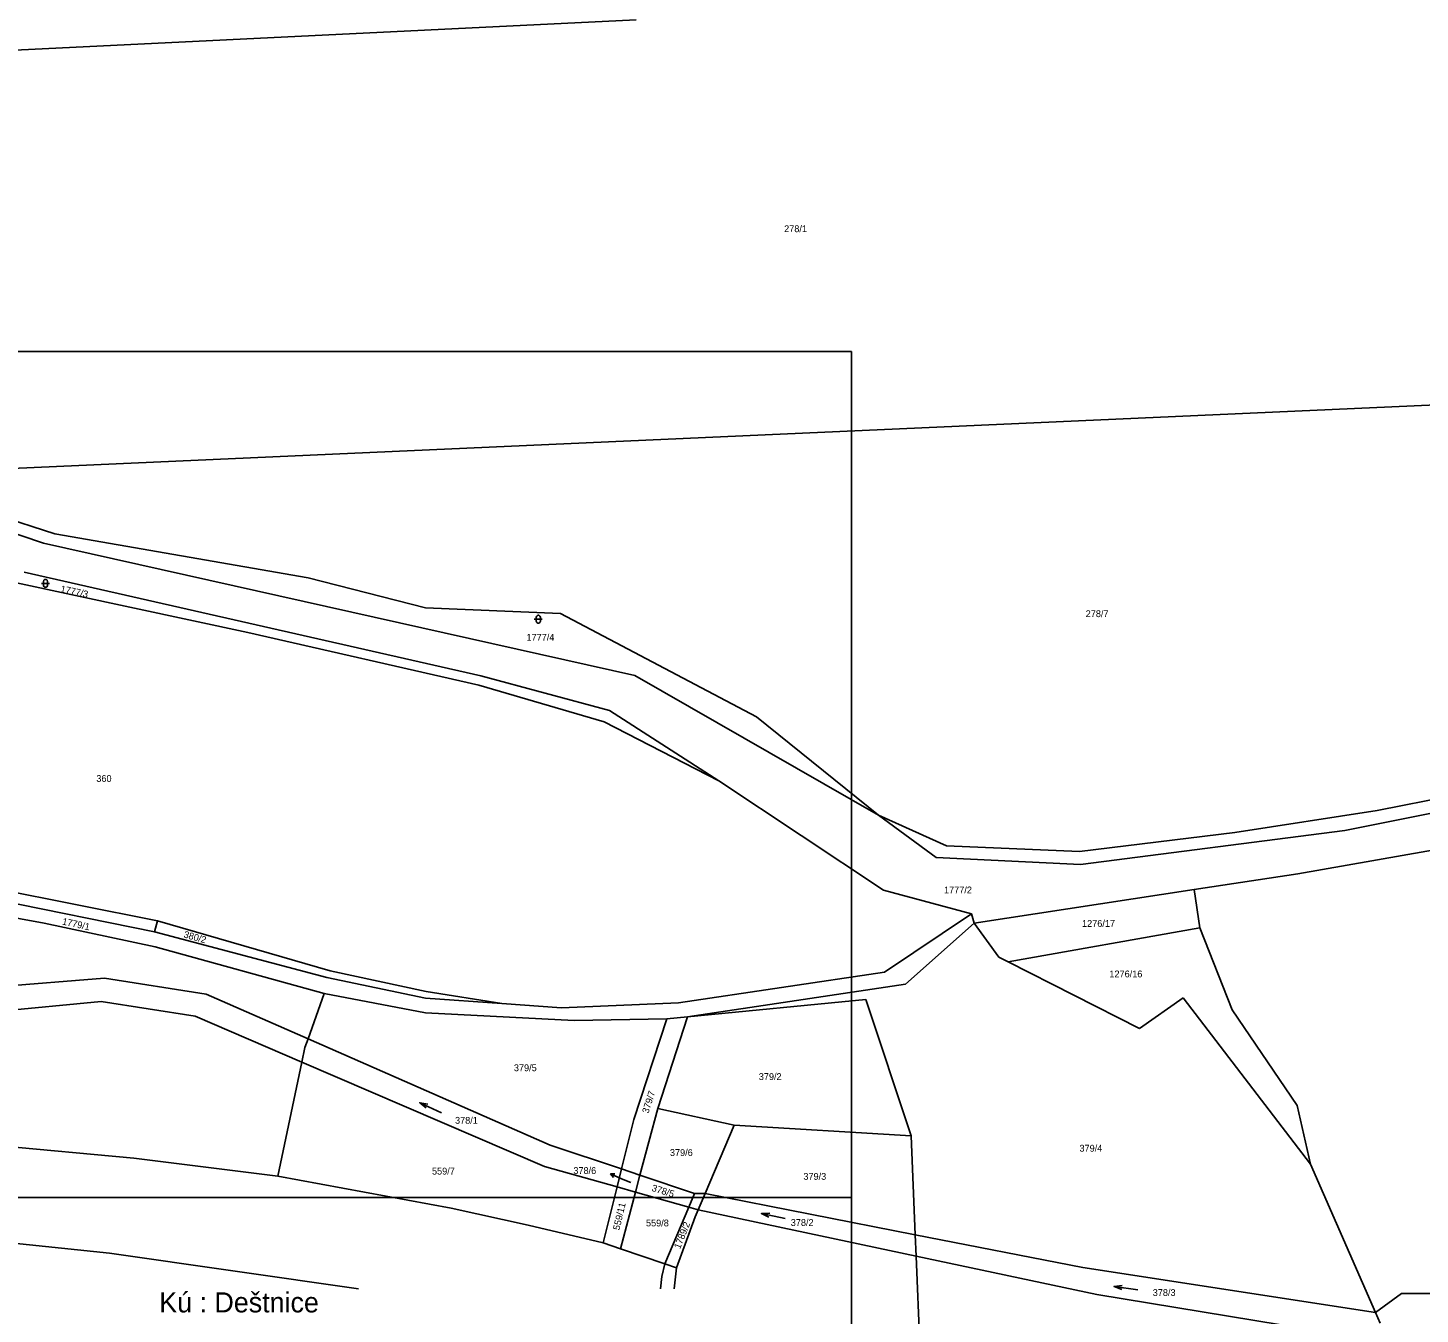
# Model space of a CAD drawing. Extents: x -799786 to -795190, y -1021716 to -1017834.
# Drawn here: x -798625.3 to -798278.5, y -1019029 to -1018708.6 of the extents above; entities that cross this region are included whole.
import ezdxf

# ---------------------------------------------------------------- set-up
doc = ezdxf.new("R2010")
doc.units = 0
for name, color, linetype in [('Default', 7, 'Continuous'), ('KLADY_ZMVM', 7, 'Continuous'), ('KN_HRANICE', 7, 'Continuous'), ('KN_KULTURY', 7, 'Continuous'), ('KN_PARCELY', 7, 'Continuous'), ('KN_SLUCKY', 7, 'Continuous'), ('LEGENDA', 7, 'Continuous')]:
    doc.layers.add(name, color=color, linetype=linetype)

# ---------------------------------------------------------------- blocks, each defined once
blk = doc.blocks.new('316')
at = {"layer": 'Default'}
for points in [[(-1, 1), (0.27, 1), (1, 1)], [(-0.5, 1.5), (-0.4, 1.79), (-0.15, 1.97), (0.16, 1.97), (0.41, 1.79), (0.51, 1.5), (0.51, 0.5), (0.41, 0.21), (0.16, 0.03), (-0.15, 0.03), (-0.4, 0.21), (-0.5, 0.5), (-0.5, 1.5)]]:
    blk.add_lwpolyline(points, dxfattribs=at)
blk = doc.blocks.new('802')
at = {"layer": 'Default'}
blk.add_line((-3, 0), (3, 0), dxfattribs=at)
blk.add_lwpolyline([(1, 0.5), (3, 0), (1, -0.5)], dxfattribs=at)
blk = doc.blocks.new('10292')
at = {"layer": 'Default'}
blk.add_line((0, 3), (0, 0), dxfattribs=at)
blk.add_lwpolyline([(-0.5, 2), (0, 3), (0.5, 2)], dxfattribs=at)

msp = doc.modelspace()

# ---------------------------------------------------------------- linework, layer by layer
at = {"layer": 'KLADY_ZMVM'}
msp.add_lwpolyline([(-799375, -1019000), (-798750, -1019000), (-798420.18, -1019000)], dxfattribs=at)
at = {"layer": 'KN_HRANICE'}
for p, q in [((-798628.58, -1018714.18), (-798473.83, -1018706.61)), ((-798648.58, -1018819.28), (-798164.43, -1018797.57)), ((-798670.97, -1018817.82), (-798618.58, -1018834.64)), ((-798670.05, -1018820.82), (-798621.41, -1018836.96)), ((-798621.41, -1018836.96), (-798474.17, -1018869.95)), ((-798618.58, -1018834.64), (-798555.54, -1018845.61)), ((-798628.2, -1018846.85), (-798570.58, -1018859.25)), ((-798626.28, -1018844.22), (-798512.51, -1018870.06)), ((-798555.54, -1018845.61), (-798526.25, -1018853.09)), ((-798526.25, -1018853.09), (-798492.65, -1018854.49)), ((-798492.65, -1018854.49), (-798443.82, -1018880.26)), ((-798570.58, -1018859.25), (-798513.02, -1018872.39)), ((-798512.51, -1018870.06), (-798480.48, -1018878.64)), ((-798474.17, -1018869.95), (-798413.42, -1018904.71)), ((-798513.02, -1018872.39), (-798481.79, -1018881.47)), ((-798289.26, -1018903.57), (-798140.92, -1018874.27)), ((-798480.48, -1018878.64), (-798453.21, -1018896.22)), ((-798481.79, -1018881.47), (-798453.21, -1018896.22)), ((-798443.82, -1018880.26), (-798413.42, -1018904.71)), ((-798297.3, -1018908.51), (-798181.63, -1018885.44)), ((-798453.21, -1018896.22), (-798412.19, -1018923.42)), ((-798413.42, -1018904.71), (-798399.11, -1018915.28)), ((-798413.42, -1018904.71), (-798396.51, -1018912.35)), ((-798324.7, -1018909.02), (-798289.26, -1018903.57)), ((-798309.02, -1018919.33), (-798225.73, -1018904.69)), ((-798363.41, -1018913.79), (-798324.7, -1018909.02)), ((-798363.16, -1018917), (-798297.3, -1018908.51)), ((-798396.51, -1018912.35), (-798363.41, -1018913.79)), ((-798399.11, -1018915.28), (-798363.16, -1018917)), ((-798334.83, -1018923.26), (-798309.02, -1018919.33)), ((-798646.5, -1018923.14), (-798593.8, -1018933.78)), ((-798644.85, -1018920.76), (-798593.08, -1018931.09)), ((-798412.19, -1018923.42), (-798390.27, -1018929.32)), ((-798389.65, -1018931.6), (-798334.83, -1018923.26)), ((-798333.38, -1018932.83), (-798334.83, -1018923.26)), ((-798646.74, -1018926.95), (-798621.31, -1018931.61)), ((-798411.98, -1018943.8), (-798390.27, -1018929.32)), ((-798390.27, -1018929.32), (-798389.65, -1018931.6)), ((-798621.31, -1018931.61), (-798593.59, -1018937.5)), ((-798593.08, -1018931.09), (-798593.8, -1018933.78)), ((-798593.8, -1018933.78), (-798550.83, -1018945.14)), ((-798593.08, -1018931.09), (-798550.03, -1018943.53)), ((-798406.71, -1018946.8), (-798389.65, -1018931.6)), ((-798383.44, -1018940.08), (-798389.65, -1018931.6)), ((-798333.38, -1018932.83), (-798381.11, -1018941.26)), ((-798593.59, -1018937.5), (-798551.56, -1018949.18)), ((-798381.11, -1018941.26), (-798383.44, -1018940.08)), ((-798550.03, -1018943.53), (-798526.1, -1018948.66)), ((-798463.3, -1018951.51), (-798411.98, -1018943.8)), ((-798348.39, -1018957.83), (-798381.11, -1018941.26)), ((-798653.61, -1018949.12), (-798606.28, -1018945.31)), ((-798606.28, -1018945.31), (-798580.93, -1018949.34)), ((-798550.83, -1018945.14), (-798526.25, -1018950.31)), ((-798461.06, -1018954.98), (-798406.71, -1018946.8)), ((-798639.41, -1018954.22), (-798607.1, -1018951.14)), ((-798607.1, -1018951.14), (-798583.64, -1018954.81)), ((-798580.93, -1018949.34), (-798555.55, -1018960.46)), ((-798551.56, -1018949.18), (-798555.55, -1018960.46)), ((-798551.56, -1018949.18), (-798526.25, -1018953.93)), ((-798526.25, -1018950.31), (-798507.23, -1018951.65)), ((-798526.1, -1018948.66), (-798507.23, -1018951.65)), ((-798492.44, -1018952.69), (-798463.3, -1018951.51)), ((-798461.06, -1018954.98), (-798416.56, -1018950.62)), ((-798405.32, -1018984.59), (-798416.56, -1018950.62)), ((-798337.55, -1018950.26), (-798348.39, -1018957.83)), ((-798305.84, -1018991.62), (-798337.55, -1018950.26)), ((-798583.64, -1018954.81), (-798557.08, -1018966.24)), ((-798526.25, -1018953.93), (-798489.23, -1018955.9)), ((-798507.23, -1018951.65), (-798492.44, -1018952.69)), ((-798468.45, -1018977.76), (-798461.06, -1018954.98)), ((-798466.19, -1018955.48), (-798461.06, -1018954.98)), ((-798489.23, -1018955.9), (-798466.19, -1018955.48)), ((-798466.19, -1018955.48), (-798474.39, -1018980.52)), ((-798555.55, -1018960.46), (-798556.31, -1018962.63)), ((-798555.55, -1018960.46), (-798495.22, -1018986.9)), ((-798556.31, -1018962.63), (-798557.08, -1018966.24)), ((-798557.08, -1018966.24), (-798563.11, -1018994.64)), ((-798557.08, -1018966.24), (-798496.64, -1018992.23)), ((-798468.45, -1018977.76), (-798472.87, -1018994.39)), ((-798449.39, -1018981.94), (-798468.45, -1018977.76)), ((-798474.39, -1018980.52), (-798477.47, -1018992.85)), ((-798449.39, -1018981.94), (-798456.64, -1018999)), ((-798449.39, -1018981.94), (-798405.32, -1018984.59)), ((-798659.98, -1018984.53), (-798598.93, -1018990.13)), ((-798404.31, -1019009.25), (-798405.32, -1018984.59)), ((-798495.22, -1018986.9), (-798477.47, -1018992.85)), ((-798598.93, -1018990.13), (-798563.11, -1018994.64)), ((-798496.64, -1018992.23), (-798478.58, -1018997.32)), ((-798477.47, -1018992.85), (-798478.58, -1018997.32)), ((-798477.47, -1018992.85), (-798472.87, -1018994.39)), ((-798305.84, -1018991.62), (-798289.67, -1019028.59)), ((-798563.11, -1018994.64), (-798519.87, -1019002.61)), ((-798472.87, -1018994.39), (-798473.99, -1018998.61)), ((-798472.87, -1018994.39), (-798459.27, -1018998.94)), ((-798478.58, -1018997.32), (-798482.07, -1019011.28)), ((-798478.58, -1018997.32), (-798473.99, -1018998.61)), ((-798473.99, -1018998.61), (-798477.75, -1019012.75)), ((-798473.99, -1018998.61), (-798460.7, -1019002.36)), ((-798459.27, -1018998.94), (-798460.7, -1019002.36)), ((-798459.27, -1018998.94), (-798456.64, -1018999)), ((-798456.64, -1018999), (-798404.31, -1019009.25)), ((-798519.87, -1019002.61), (-798500.68, -1019006.85)), ((-798460.7, -1019002.36), (-798466.63, -1019016.52)), ((-798460.7, -1019002.36), (-798458.35, -1019003.02)), ((-798458.35, -1019003.02), (-798459.09, -1019004.76)), ((-798458.35, -1019003.02), (-798404.09, -1019014.54)), ((-798500.68, -1019006.85), (-798482.07, -1019011.28)), ((-798463.72, -1019017.51), (-798459.09, -1019004.76)), ((-798404.31, -1019009.25), (-798362.55, -1019017.42)), ((-798404.09, -1019014.54), (-798404.31, -1019009.25)), ((-798633.02, -1019010.96), (-798604.99, -1019013.85)), ((-798604.99, -1019013.85), (-798542.99, -1019022.68)), ((-798482.07, -1019011.28), (-798477.75, -1019012.75)), ((-798477.75, -1019012.75), (-798466.63, -1019016.52)), ((-798467.39, -1019019.65), (-798466.63, -1019016.52)), ((-798466.63, -1019016.52), (-798463.72, -1019017.51)), ((-798404.09, -1019014.54), (-798359.05, -1019024.1)), ((-798400.12, -1019110.95), (-798404.09, -1019014.54)), ((-798362.55, -1019017.42), (-798289.67, -1019028.59)), ((-798467.39, -1019019.65), (-798467.74, -1019022.68)), ((-798464.36, -1019022.68), (-798463.72, -1019017.51)), ((-798359.05, -1019024.1), (-798293.45, -1019034.91)), ((-798289.67, -1019028.59), (-798283.19, -1019023.84)), ((-798283.19, -1019023.84), (-798256.91, -1019023.98)), ((-798289.67, -1019028.59), (-798288.5, -1019031.25))]:
    msp.add_line(p, q, dxfattribs=at)
msp.add_lwpolyline([(-798305.84, -1018991.62), (-798309.15, -1018977.02), (-798325.36, -1018953.21), (-798333.38, -1018932.83)], dxfattribs=at)
at = {"layer": 'KN_PARCELY'}
msp.add_line((-798475.16, -1018996.24), (-798477.44, -1018995.27), dxfattribs=at)
at = {"layer": 'KN_SLUCKY'}
msp.add_line((-798456.64, -1018999), (-798458.35, -1019003.02), dxfattribs=at)
at = {"layer": 'LEGENDA'}
msp.add_lwpolyline([(-799014.18, -1018789.26), (-798420.18, -1018789.26), (-798420.18, -1019209.26), (-799014.18, -1019209.26)], close=True, dxfattribs=at)

# ---------------------------------------------------------------- block references
at = {"layer": 'KN_KULTURY'}
for p in [(-798620.92, -1018848.01), (-798498.19, -1018856.92)]:
    msp.add_blockref('316', p, dxfattribs=at)
for p, rotation in [((-798525, -1018977.61), 155.214267), ((-798439.65, -1019004.59), 168.335), ((-798351.8, -1019022.52), 172.116522)]:
    msp.add_blockref('802', p, dxfattribs=dict(at, rotation=rotation))
at = {"layer": 'KN_PARCELY', "rotation": 66.97876600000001}
msp.add_blockref('10292', (-798477.44, -1018995.27), dxfattribs=at)

# ---------------------------------------------------------------- texts
at = {"layer": 'KN_PARCELY'}
for s, height, p in [('278/1', 1.7, (-798436.95, -1018759.52)), ('278/7', 1.7, (-798361.83, -1018855.4)), ('1777/4', 1.7, (-798501.13, -1018861.28)), ('360', 1.7, (-798608.28, -1018896.44)), ('1777/2', 1.7, (-798397.12, -1018924.21)), ('1276/17', 1.7, (-798362.74, -1018932.56)), ('1276/16', 1.7, (-798355.93, -1018945.13)), ('379/5', 1.7, (-798504.27, -1018968.5)), ('379/2', 1.7, (-798443.26, -1018970.69)), ('378/1', 1.7, (-798518.93, -1018981.59)), ('379/6', 1.7, (-798465.4, -1018989.62)), ('379/4', 1.7, (-798363.38, -1018988.54)), ('559/7', 1.7, (-798524.67, -1018994.25)), ('378/6', 1.7, (-798489.45, -1018994.1)), ('378/6', 0.1, (-798475.4, -1018996.24)), ('379/3', 1.7, (-798432.15, -1018995.55)), ('559/8', 1.7, (-798471.36, -1019007.16)), ('378/2', 1.7, (-798435.3, -1019007.04)), ('378/3', 1.7, (-798345.13, -1019024.49))]:
    msp.add_text(s, height=height, dxfattribs=at).set_placement(p)
for s, rotation, p in [('1777/3', 347.9, (-798617.32, -1018849.14)), ('1779/1', 347.843, (-798616.9, -1018931.96)), ('380/2', 344.577, (-798586.66, -1018935.16)), ('379/7', 72.021, (-798470.77, -1018979.15)), ('378/5', 342.743, (-798470.07, -1018998.29)), ('559/11', 76.891, (-798477.97, -1019008.23)), ('1789/2', 68.182, (-798462.89, -1019012.91))]:
    msp.add_text(s, height=1.7, rotation=rotation, dxfattribs=at).set_placement(p)
at = {"layer": 'LEGENDA'}
msp.add_text('Kú : Deštnice', height=5, dxfattribs=at).set_placement((-798592.61, -1019028.58))

doc.saveas('drawing.dxf')
